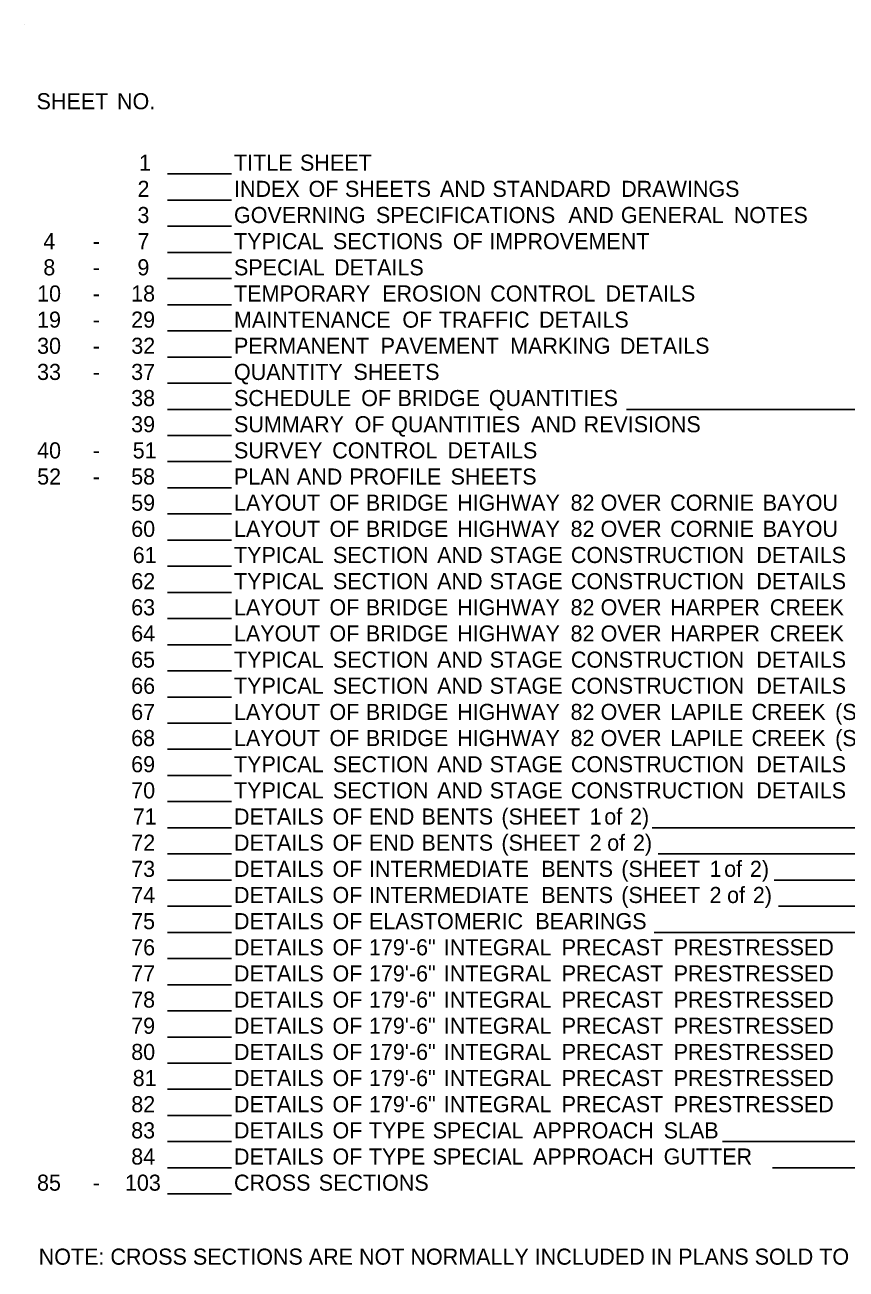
# Model space of a CAD drawing. Extents: x -1392 to 1630, y -1031 to 935.
# Drawn here: x -1392 to -779, y -232 to 696 of the extents above; entities that cross this region are included whole.
import ezdxf

# ---------------------------------------------------------------- set-up
doc = ezdxf.new("R2010")
doc.units = 0
doc.layers.add('Default', color=7, linetype='Continuous')

msp = doc.modelspace()

# ---------------------------------------------------------------- linework, layer by layer
at = {"layer": 'Default'}
for p, q in [((-1391.74, 696), (-1391.74, 696)), ((-1285.47, 584.85), (-1237.69, 584.85)), ((-1285.47, 565.35), (-1237.69, 565.35)), ((-1285.47, 545.85), (-1237.69, 545.85)), ((-1285.47, 526.35), (-1237.69, 526.35)), ((-1285.47, 506.85), (-1237.69, 506.85)), ((-1285.47, 487.35), (-1237.69, 487.35)), ((-1285.47, 467.85), (-1237.69, 467.85)), ((-1285.47, 448.35), (-1237.69, 448.35)), ((-1285.47, 428.85), (-1237.69, 428.85)), ((-1285.47, 409.35), (-1237.69, 409.35)), ((-942.93, 409.35), (-203.68, 409.35)), ((-1285.47, 389.85), (-1237.69, 389.85)), ((-1285.47, 370.35), (-1237.69, 370.35)), ((-1285.47, 350.85), (-1237.69, 350.85)), ((-1285.47, 331.35), (-1237.69, 331.35)), ((-1285.47, 311.85), (-1237.69, 311.85)), ((-1285.47, 292.35), (-1237.69, 292.35)), ((-1285.47, 272.85), (-1237.69, 272.85)), ((-1285.47, 253.35), (-1237.69, 253.35)), ((-1285.47, 233.85), (-1237.69, 233.85)), ((-1285.47, 214.35), (-1237.69, 214.35)), ((-1285.47, 194.85), (-1237.69, 194.85)), ((-1285.47, 175.35), (-1237.69, 175.35)), ((-1285.47, 155.85), (-1237.69, 155.85)), ((-1285.47, 136.35), (-1237.69, 136.35)), ((-1285.47, 116.85), (-1237.69, 116.85)), ((-1285.47, 97.35), (-1237.69, 97.35)), ((-923.8, 97.35), (-203.68, 97.35)), ((-1285.47, 77.85), (-1237.69, 77.85)), ((-919.33, 77.85), (-203.68, 77.85)), ((-1285.47, 58.35), (-1237.69, 58.35)), ((-832.91, 58.35), (-203.68, 58.35)), ((-1285.47, 38.85), (-1237.69, 38.85)), ((-829.47, 38.85), (-203.68, 38.85)), ((-1285.47, 19.35), (-1237.69, 19.35)), ((-922.42, 19.35), (-203.68, 19.35)), ((-1285.47, -0.15), (-1237.69, -0.15)), ((-1285.47, -19.65), (-1237.69, -19.65)), ((-1285.47, -39.15), (-1237.69, -39.15)), ((-1285.47, -58.65), (-1237.69, -58.65)), ((-1285.47, -78.15), (-1237.69, -78.15)), ((-1285.47, -97.65), (-1237.69, -97.65)), ((-1285.47, -117.15), (-1237.69, -117.15)), ((-1285.47, -136.65), (-1237.69, -136.65)), ((-871.3, -136.65), (-203.68, -136.65)), ((-1285.47, -156.15), (-1237.69, -156.15)), ((-834.06, -156.15), (-203.68, -156.15)), ((-1285.47, -175.65), (-1237.69, -175.65))]:
    msp.add_line(p, q, dxfattribs=at)

# ---------------------------------------------------------------- texts
for s, p in [('SHEET', (-1383.04, 633.08)), (' NO.', (-1327.48, 633.08)), ('1', (-1306.62, 587.25)), ('TITLE', (-1235.74, 587.25)), (' SHEET', (-1190.99, 587.25)), ('2', (-1307.72, 567.75)), ('INDEX', (-1235.74, 567.75)), (' OF', (-1184.6, 567.75)), (' SHEETS', (-1157.43, 567.75)), (' AND', (-1086.56, 567.75)), (' STANDARD', (-1047.39, 567.75)), (' DRAWINGS', (-951.39, 567.75)), ('3', (-1307.78, 548.25)), ('GOVERNING', (-1235.74, 548.25)), (' SPECIFICATIONS', (-1134.31, 548.25)), (' AND', (-990.77, 548.25)), (' GENERAL', (-951.61, 548.25)), (' NOTES', (-867.41, 548.25)), ('4', (-1377.96, 528.75)), ('7', (-1307.78, 528.75)), ('TYPICAL', (-1235.74, 528.75)), (' SECTIONS', (-1166.45, 528.75)), (' OF', (-1076.95, 528.75)), (' IMPROVEMENT', (-1049.78, 528.75)), ('-', (-1341.13, 528.75)), ('8', (-1377.99, 509.25)), ('9', (-1307.79, 509.25)), ('SPECIAL', (-1235.74, 509.25)), (' DETAILS', (-1165.51, 509.25)), ('-', (-1341.13, 509.25)), ('10', (-1382.62, 489.75)), ('18', (-1312.45, 489.75)), ('TEMPORARY', (-1235.74, 489.75)), (' EROSION', (-1129.65, 489.75)), (' CONTROL', (-1049.04, 489.75)), (' DETAILS', (-963, 489.75)), ('-', (-1341.13, 489.75)), ('19', (-1382.65, 470.25)), ('29', (-1312.45, 470.25)), ('MAINTENANCE', (-1235.74, 470.25)), (' OF', (-1114.59, 470.25)), (' TRAFFIC', (-1087.41, 470.25)), (' DETAILS', (-1012.63, 470.25)), ('-', (-1341.13, 470.25)), ('30', (-1382.62, 450.75)), ('-', (-1341.13, 450.75)), ('32', (-1312.38, 450.75)), ('PERMANENT', (-1235.74, 450.75)), (' PAVEMENT', (-1130.8, 450.75)), (' MARKING', (-1034.23, 450.75)), (' DETAILS', (-952.37, 450.75)), ('33', (-1382.64, 431.25)), ('-', (-1341.13, 431.25)), ('37', (-1312.44, 431.25)), ('QUANTITY', (-1235.74, 431.25)), (' SHEETS', (-1151.09, 431.25)), ('38', (-1312.45, 411.75)), ('SCHEDULE', (-1235.74, 411.75)), (' OF', (-1145.32, 411.75)), (' BRIDGE', (-1118.15, 411.75)), (' QUANTITIES', (-1050.1, 411.75)), ('39', (-1312.45, 392.25)), ('SUMMARY', (-1235.74, 392.25)), (' OF', (-1150.16, 392.25)), (' QUANTITIES', (-1122.98, 392.25)), (' AND', (-1018.59, 392.25)), (' REVISIONS', (-979.42, 392.25)), ('40', (-1382.62, 372.75)), ('51', (-1311.28, 372.75)), ('SURVEY', (-1235.74, 372.75)), (' CONTROL', (-1166.91, 372.75)), (' DETAILS', (-1080.87, 372.75)), ('-', (-1341.13, 372.75)), ('52', (-1382.58, 353.25)), ('58', (-1312.45, 353.25)), ('PLAN', (-1235.74, 353.25)), (' AND', (-1193.31, 353.25)), (' PROFILE', (-1154.15, 353.25)), (' SHEETS', (-1078.64, 353.25)), ('-', (-1341.13, 353.25)), ('59', (-1312.45, 333.75)), ('LAYOUT', (-1235.74, 333.75)), (' OF', (-1168.99, 333.75)), (' BRIDGE', (-1141.82, 333.75)), (' HIGHWAY', (-1073.77, 333.75)), (' 82', (-989.13, 333.75)), (' OVER', (-966.72, 333.75)), (' CORNIE', (-914.77, 333.75)), (' BAYOU', (-845.8, 333.75)), ('60', (-1312.42, 314.25)), ('LAYOUT', (-1235.74, 314.25)), (' OF', (-1168.99, 314.25)), (' BRIDGE', (-1141.82, 314.25)), (' HIGHWAY', (-1073.77, 314.25)), (' 82', (-989.13, 314.25)), (' OVER', (-966.72, 314.25)), (' CORNIE', (-914.77, 314.25)), (' BAYOU', (-845.8, 314.25)), ('61', (-1311.28, 294.75)), ('TYPICAL', (-1235.74, 294.75)), (' SECTION', (-1166.45, 294.75)), (' AND', (-1088.63, 294.75)), (' STAGE', (-1049.47, 294.75)), (' CONSTRUCTION', (-988.86, 294.75)), (' DETAILS', (-850.51, 294.75)), ('62', (-1312.38, 275.25)), ('TYPICAL', (-1235.74, 275.25)), (' SECTION', (-1166.45, 275.25)), (' AND', (-1088.63, 275.25)), (' STAGE', (-1049.47, 275.25)), (' CONSTRUCTION', (-988.86, 275.25)), (' DETAILS', (-850.51, 275.25)), ('63', (-1312.44, 255.75)), ('LAYOUT', (-1235.74, 255.75)), (' OF', (-1168.99, 255.75)), (' BRIDGE', (-1141.82, 255.75)), (' HIGHWAY', (-1073.77, 255.75)), (' 82', (-989.13, 255.75)), (' OVER', (-966.72, 255.75)), (' HARPER', (-914.77, 255.75)), (' CREEK', (-840.45, 255.75)), ('64', (-1312.42, 236.25)), ('LAYOUT', (-1235.74, 236.25)), (' OF', (-1168.99, 236.25)), (' BRIDGE', (-1141.82, 236.25)), (' HIGHWAY', (-1073.77, 236.25)), (' 82', (-989.13, 236.25)), (' OVER', (-966.72, 236.25)), (' HARPER', (-914.77, 236.25)), (' CREEK', (-840.45, 236.25)), ('65', (-1312.49, 216.75)), ('TYPICAL', (-1235.74, 216.75)), (' SECTION', (-1166.45, 216.75)), (' AND', (-1088.63, 216.75)), (' STAGE', (-1049.47, 216.75)), (' CONSTRUCTION', (-988.86, 216.75)), (' DETAILS', (-850.51, 216.75)), ('66', (-1312.44, 197.25)), ('TYPICAL', (-1235.74, 197.25)), (' SECTION', (-1166.45, 197.25)), (' AND', (-1088.63, 197.25)), (' STAGE', (-1049.47, 197.25)), (' CONSTRUCTION', (-988.86, 197.25)), (' DETAILS', (-850.51, 197.25)), ('67', (-1312.44, 177.75)), ('LAYOUT', (-1235.74, 177.75)), (' OF', (-1168.99, 177.75)), (' BRIDGE', (-1141.82, 177.75)), (' HIGHWAY', (-1073.77, 177.75)), (' 82', (-989.13, 177.75)), (' OVER', (-966.72, 177.75)), (' LAPILE', (-914.77, 177.75)), (' CREEK', (-854.16, 177.75)), (' (SHEET', (-791.76, 177.75)), ('68', (-1312.45, 158.25)), ('LAYOUT', (-1235.74, 158.25)), (' OF', (-1168.99, 158.25)), (' BRIDGE', (-1141.82, 158.25)), (' HIGHWAY', (-1073.77, 158.25)), (' 82', (-989.13, 158.25)), (' OVER', (-966.72, 158.25)), (' LAPILE', (-914.77, 158.25)), (' CREEK', (-854.16, 158.25)), (' (SHEET', (-791.76, 158.25)), ('69', (-1312.45, 138.75)), ('TYPICAL', (-1235.74, 138.75)), (' SECTION', (-1166.45, 138.75)), (' AND', (-1088.63, 138.75)), (' STAGE', (-1049.47, 138.75)), (' CONSTRUCTION', (-988.86, 138.75)), (' DETAILS', (-850.51, 138.75)), ('70', (-1312.42, 119.25)), ('TYPICAL', (-1235.74, 119.25)), (' SECTION', (-1166.45, 119.25)), (' AND', (-1088.63, 119.25)), (' STAGE', (-1049.47, 119.25)), (' CONSTRUCTION', (-988.86, 119.25)), (' DETAILS', (-850.51, 119.25)), ('71', (-1311.28, 99.75)), ('DETAILS', (-1235.74, 99.75)), (' OF', (-1166.73, 99.75)), (' END', (-1139.56, 99.75)), (' BENTS', (-1100.39, 99.75)), (' (SHEET', (-1040.7, 99.75)), (' 1', (-974.9, 99.75)), (' of', (-964, 99.75)), (' 2)', (-944.79, 99.75)), (' (SHEET', (-1040.7, 80.25)), (' of', (-961.81, 80.25)), (' 2)', (-942.59, 80.25)), ('72', (-1312.38, 80.25)), ('DETAILS', (-1235.74, 80.25)), (' OF', (-1166.73, 80.25)), (' END', (-1139.56, 80.25)), (' BENTS', (-1100.39, 80.25)), (' 2', (-974.9, 80.25)), ('73', (-1312.44, 60.75)), ('DETAILS', (-1235.74, 60.75)), (' OF', (-1166.73, 60.75)), (' INTERMEDIATE', (-1139.56, 60.75)), (' BENTS', (-1010.96, 60.75)), (' (SHEET', (-951.27, 60.75)), (' 1', (-885.46, 60.75)), (' of', (-874.57, 60.75)), (' 2)', (-855.35, 60.75)), ('74', (-1312.42, 41.25)), ('DETAILS', (-1235.74, 41.25)), (' OF', (-1166.73, 41.25)), (' INTERMEDIATE', (-1139.56, 41.25)), (' BENTS', (-1010.96, 41.25)), (' (SHEET', (-951.27, 41.25)), (' 2', (-885.46, 41.25)), (' of', (-872.38, 41.25)), (' 2)', (-853.16, 41.25)), ('75', (-1312.49, 21.75)), ('DETAILS', (-1235.74, 21.75)), (' OF', (-1166.73, 21.75)), (' ELASTOMERIC', (-1139.56, 21.75)), (' BEARINGS', (-1015.38, 21.75)), ('76', (-1312.44, 2.25)), ('DETAILS', (-1235.74, 2.25)), (' OF', (-1166.73, 2.25)), (' 179\'-6"', (-1139.56, 2.25)), (' INTEGRAL', (-1083.67, 2.25)), (' PRECAST', (-995.76, 2.25)), (' PRESTRESSED', (-912.23, 2.25)), ('77', (-1312.44, -17.25)), ('DETAILS', (-1235.74, -17.25)), (' OF', (-1166.73, -17.25)), (' 179\'-6"', (-1139.56, -17.25)), (' INTEGRAL', (-1083.67, -17.25)), (' PRECAST', (-995.76, -17.25)), (' PRESTRESSED', (-912.23, -17.25)), ('78', (-1312.45, -36.75)), ('DETAILS', (-1235.74, -36.75)), (' OF', (-1166.73, -36.75)), (' 179\'-6"', (-1139.56, -36.75)), (' INTEGRAL', (-1083.67, -36.75)), (' PRECAST', (-995.76, -36.75)), (' PRESTRESSED', (-912.23, -36.75)), ('79', (-1312.45, -56.25)), ('DETAILS', (-1235.74, -56.25)), (' OF', (-1166.73, -56.25)), (' 179\'-6"', (-1139.56, -56.25)), (' INTEGRAL', (-1083.67, -56.25)), (' PRECAST', (-995.76, -56.25)), (' PRESTRESSED', (-912.23, -56.25)), ('80', (-1312.42, -75.75)), ('DETAILS', (-1235.74, -75.75)), (' OF', (-1166.73, -75.75)), (' 179\'-6"', (-1139.56, -75.75)), (' INTEGRAL', (-1083.67, -75.75)), (' PRECAST', (-995.76, -75.75)), (' PRESTRESSED', (-912.23, -75.75)), ('81', (-1311.28, -95.25)), ('DETAILS', (-1235.74, -95.25)), (' OF', (-1166.73, -95.25)), (' 179\'-6"', (-1139.56, -95.25)), (' INTEGRAL', (-1083.67, -95.25)), (' PRECAST', (-995.76, -95.25)), (' PRESTRESSED', (-912.23, -95.25)), ('82', (-1312.38, -114.75)), ('DETAILS', (-1235.74, -114.75)), (' OF', (-1166.73, -114.75)), (' 179\'-6"', (-1139.56, -114.75)), (' INTEGRAL', (-1083.67, -114.75)), (' PRECAST', (-995.76, -114.75)), (' PRESTRESSED', (-912.23, -114.75)), ('83', (-1312.44, -134.25)), ('DETAILS', (-1235.74, -134.25)), (' OF', (-1166.73, -134.25)), (' TYPE', (-1139.56, -134.25)), (' SPECIAL', (-1092, -134.25)), (' APPROACH', (-1017.11, -134.25)), (' SLAB', (-919.69, -134.25)), ('84', (-1312.42, -153.75)), ('DETAILS', (-1235.74, -153.75)), (' OF', (-1166.73, -153.75)), (' TYPE', (-1139.56, -153.75)), (' SPECIAL', (-1092, -153.75)), (' APPROACH', (-1017.11, -153.75)), (' GUTTER', (-919.69, -153.75)), ('85', (-1382.69, -173.25)), ('103', (-1317.1, -173.25)), ('CROSS', (-1235.74, -173.25)), (' SECTIONS', (-1176.98, -173.25)), ('-', (-1341.13, -173.25)), ('NOTE: CROSS SECTIONS ARE NOT NORMALLY INCLUDED IN PLANS SOLD TO PERSPECTIVE BIDDERS, BUT MAY BE HAD UPON REQUEST.', (-1381.43, -228.41))]:
    msp.add_text(s, height=12, dxfattribs=at).set_placement(p)

doc.saveas('drawing.dxf')
